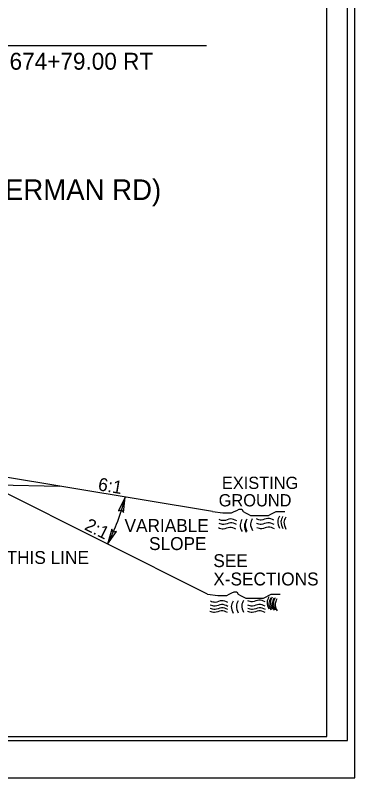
# Model space of a CAD drawing. Extents: x 2294370 to 2294957, y 719276 to 719941.
# Drawn here: x 2294750.8 to 2294792, y 719276.3 to 719368.6 of the extents above; entities that cross this region are included whole.
import ezdxf

# ---------------------------------------------------------------- set-up
doc = ezdxf.new("R2010")
doc.units = 0
for name, color, linetype in [('Old_Level_1', 7, 'Continuous'), ('Old_Level_11', 7, 'Continuous'), ('Old_Level_2', 7, 'Continuous'), ('Old_Level_3', 7, 'Continuous'), ('Sheet Cutting Line CELL', 7, 'Continuous'), ('Sheet Plot Border Inside CELL', 7, 'Continuous'), ('Sheet Plot Border Outside CELL', 7, 'Continuous'), ('Sheet Typical CELL', 7, 'Continuous'), ('Typical Hinge Slope Arterial CELL', 7, 'Continuous')]:
    doc.layers.add(name, color=color, linetype=linetype)

msp = doc.modelspace()

# ---------------------------------------------------------------- linework, layer by layer
at = {"layer": 'Old_Level_1'}
msp.add_line((2294740.816, 719311.96), (2294756.206, 719311.637), dxfattribs=at)
at = {"layer": 'Old_Level_11'}
msp.add_line((2294773.963, 719364.93), (2294713.602, 719364.929), dxfattribs=at)
for points in [[(2294763.92, 719308.46), (2294764.131, 719310.316), (2294763.299, 719308.63), (2294763.679, 719308.765)], [(2294762.493, 719306.42), (2294761.997, 719304.619), (2294763.081, 719306.155), (2294762.684, 719306.081)]]:
    msp.add_lwpolyline(points, close=True, dxfattribs=at)
at = {"layer": 'Old_Level_2'}
for points in [[(2294777.65, 719307.449), (2294776.896, 719307.664), (2294776.105, 719307.461), (2294775.53, 719307.588)], [(2294777.65, 719307.449), (2294776.896, 719307.664), (2294776.105, 719307.461), (2294775.53, 719307.588)], [(2294778.272, 719307.592), (2294778.06, 719306.97), (2294778.289, 719306.149)], [(2294778.788, 719307.506), (2294778.577, 719306.884), (2294778.805, 719306.062)], [(2294778.879, 719307.647), (2294778.667, 719307.025), (2294778.893, 719306.201)], [(2294778.879, 719307.647), (2294778.667, 719307.025), (2294778.893, 719306.201)], [(2294779.534, 719307.697), (2294779.325, 719307.077), (2294779.549, 719306.254)], [(2294779.534, 719307.697), (2294779.325, 719307.077), (2294779.549, 719306.254)], [(2294782.163, 719307.52), (2294781.414, 719307.736), (2294780.616, 719307.533), (2294780.046, 719307.662)], [(2294782.163, 719307.52), (2294781.414, 719307.736), (2294780.616, 719307.533), (2294780.046, 719307.662)], [(2294782.828, 719308.004), (2294782.615, 719307.382), (2294782.843, 719306.561)], [(2294782.828, 719308.004), (2294782.615, 719307.382), (2294782.843, 719306.561)], [(2294783.217, 719307.963), (2294783.008, 719307.341), (2294783.236, 719306.517)], [(2294783.217, 719307.963), (2294783.008, 719307.341), (2294783.236, 719306.517)], [(2294783.582, 719307.892), (2294783.37, 719307.272), (2294783.599, 719306.448)], [(2294783.582, 719307.892), (2294783.37, 719307.272), (2294783.599, 719306.448)], [(2294777.554, 719306.431), (2294776.802, 719306.646), (2294776.006, 719306.443), (2294775.434, 719306.572)], [(2294777.554, 719306.431), (2294776.802, 719306.646), (2294776.006, 719306.443), (2294775.434, 719306.572)], [(2294777.63, 719306.977), (2294776.877, 719307.194), (2294776.085, 719306.989), (2294775.511, 719307.118)], [(2294777.63, 719306.977), (2294776.877, 719307.194), (2294776.085, 719306.989), (2294775.511, 719307.118)], [(2294782.168, 719306.997), (2294781.414, 719307.21), (2294780.623, 719307.007), (2294780.05, 719307.136)], [(2294782.168, 719306.997), (2294781.414, 719307.21), (2294780.623, 719307.007), (2294780.05, 719307.136)], [(2294782.226, 719306.469), (2294781.474, 719306.681), (2294780.676, 719306.483), (2294780.104, 719306.609)], [(2294782.226, 719306.469), (2294781.474, 719306.681), (2294780.676, 719306.483), (2294780.104, 719306.609)], [(2294781.544, 719298.222), (2294781.331, 719297.6), (2294781.559, 719296.778)], [(2294781.933, 719298.181), (2294781.724, 719297.559), (2294781.952, 719296.735)], [(2294776.563, 719297.086), (2294775.809, 719297.303), (2294775.018, 719297.098), (2294774.443, 719297.227)], [(2294776.563, 719297.086), (2294775.809, 719297.303), (2294775.018, 719297.098), (2294774.443, 719297.227)], [(2294776.583, 719297.558), (2294775.829, 719297.773), (2294775.037, 719297.57), (2294774.463, 719297.697)], [(2294776.583, 719297.558), (2294775.829, 719297.773), (2294775.037, 719297.57), (2294774.463, 719297.697)], [(2294777.204, 719297.702), (2294776.993, 719297.079), (2294777.221, 719296.258)], [(2294777.204, 719297.702), (2294776.993, 719297.079), (2294777.221, 719296.258)], [(2294777.811, 719297.756), (2294777.6, 719297.134), (2294777.826, 719296.31)], [(2294777.811, 719297.756), (2294777.6, 719297.134), (2294777.826, 719296.31)], [(2294778.467, 719297.806), (2294778.258, 719297.186), (2294778.482, 719296.363)], [(2294778.467, 719297.806), (2294778.258, 719297.186), (2294778.482, 719296.363)], [(2294781.096, 719297.629), (2294780.346, 719297.845), (2294779.548, 719297.643), (2294778.978, 719297.772)], [(2294781.096, 719297.629), (2294780.346, 719297.845), (2294779.548, 719297.643), (2294778.978, 719297.772)], [(2294781.1, 719297.106), (2294780.347, 719297.319), (2294779.555, 719297.116), (2294778.983, 719297.245)], [(2294781.1, 719297.106), (2294780.347, 719297.319), (2294779.555, 719297.116), (2294778.983, 719297.245)], [(2294781.76, 719298.114), (2294781.547, 719297.491), (2294781.775, 719296.67)], [(2294782.149, 719298.073), (2294781.94, 719297.451), (2294782.168, 719296.626)], [(2294782.298, 719298.11), (2294782.086, 719297.49), (2294782.315, 719296.666)], [(2294782.514, 719298.001), (2294782.303, 719297.382), (2294782.531, 719296.558)], [(2294776.521, 719296.328), (2294775.769, 719296.541), (2294774.972, 719296.342), (2294774.399, 719296.469)], [(2294776.562, 719296.69), (2294775.81, 719296.905), (2294775.014, 719296.702), (2294774.442, 719296.831)], [(2294776.562, 719296.69), (2294775.81, 719296.905), (2294775.014, 719296.702), (2294774.442, 719296.831)], [(2294781.084, 719296.328), (2294780.332, 719296.541), (2294779.534, 719296.342), (2294778.962, 719296.469)], [(2294781.125, 719296.69), (2294780.373, 719296.905), (2294779.577, 719296.702), (2294779.005, 719296.831)], [(2294781.125, 719296.69), (2294780.373, 719296.905), (2294779.577, 719296.702), (2294779.005, 719296.831)]]:
    msp.add_spline(points, degree=3, dxfattribs=at)
at = {"layer": 'Sheet Cutting Line CELL'}
msp.add_line((2294455.16, 719276.338), (2294791.96, 719276.338), dxfattribs=at)
at = {"layer": 'Sheet Plot Border Inside CELL'}
msp.add_lwpolyline([(2294791.06, 719491.848), (2294457.76, 719491.848), (2294457.76, 719280.828), (2294791.06, 719280.828)], close=True, dxfattribs=at)
at = {"layer": 'Sheet Plot Border Outside CELL'}
for points in [[(2294455.16, 719276.338), (2294791.96, 719276.338), (2294791.96, 719496.338), (2294455.16, 719496.338)], [(2294791.96, 719496.338), (2294455.16, 719496.338), (2294455.16, 719276.338), (2294791.96, 719276.338)]]:
    msp.add_lwpolyline(points, close=True, dxfattribs=at)
at = {"layer": 'Sheet Typical CELL'}
msp.add_lwpolyline([(2294788.56, 719491.338), (2294488.56, 719491.338), (2294488.56, 719281.338), (2294788.56, 719281.338)], close=True, dxfattribs=at)
at = {"layer": 'Typical Hinge Slope Arterial CELL'}
for p in [(2294774.121, 719298.55), (2294774.715, 719308.552)]:
    msp.add_line(p, (2294743.816, 719313.702), dxfattribs=at)
for points in [[(2294774.715, 719308.552), (2294775.947, 719308.399), (2294776.255, 719308.399), (2294776.717, 719308.399), (2294777.025, 719308.399), (2294777.333, 719308.552), (2294777.641, 719308.706), (2294777.949, 719308.861), (2294778.257, 719308.861), (2294778.412, 719308.552), (2294778.72, 719308.399), (2294779.028, 719308.244), (2294779.336, 719308.091), (2294779.644, 719308.091), (2294779.951, 719308.091), (2294780.259, 719308.091), (2294780.567, 719308.091), (2294780.875, 719308.091), (2294781.183, 719308.091), (2294781.491, 719308.091), (2294781.799, 719308.244), (2294782.107, 719308.399), (2294782.415, 719308.552), (2294782.878, 719308.552), (2294783.186, 719308.552), (2294783.494, 719308.552)], [(2294774.121, 719298.55), (2294775.353, 719298.396), (2294775.66, 719298.396), (2294776.123, 719298.396), (2294776.431, 719298.396), (2294776.739, 719298.55), (2294777.047, 719298.704), (2294777.355, 719298.859), (2294777.663, 719298.859), (2294777.817, 719298.55), (2294778.125, 719298.396), (2294778.433, 719298.242), (2294778.741, 719298.088), (2294779.049, 719298.088), (2294779.357, 719298.088), (2294779.665, 719298.088), (2294779.973, 719298.088), (2294780.281, 719298.088), (2294780.589, 719298.088), (2294780.897, 719298.088), (2294781.205, 719298.242), (2294781.513, 719298.396), (2294781.821, 719298.55), (2294782.283, 719298.55), (2294782.591, 719298.55), (2294782.899, 719298.55)]]:
    msp.add_lwpolyline(points, dxfattribs=at)
msp.add_arc((2294736.108, 719317.563), 28.944, 333.43495, 345.5, dxfattribs=at)

# ---------------------------------------------------------------- texts
at = {"layer": 'Old_Level_1'}
for s, height, rotation, p in [('-L- Sta. 670+62.59 RT to Sta. 674+79.00 RT', 2.04545, 360, (2294713.539, 719362.051)), ('6:1', 1.5625, 350.53768, (2294760.76, 719311.148)), ('EXISTING', 1.4844, 0.00004, (2294775.849, 719311.294)), ('GROUND', 1.4844, 0.00004, (2294775.462, 719309.185)), ('2:1', 1.5625, 333.43495, (2294759.083, 719306.428)), ('SEE ', 1.5625, 359.99996, (2294774.805, 719301.837)), ('X-SECTIONS', 1.5625, 359.99996, (2294774.805, 719299.616))]:
    msp.add_text(s, height=height, rotation=rotation, dxfattribs=at).set_placement(p)
at = {"layer": 'Old_Level_11'}
msp.add_text('GRADE TO THIS LINE', height=1.5625, rotation=0.00004, dxfattribs=at).set_placement((2294738.251, 719302.221))
at = {"layer": 'Old_Level_3'}
msp.add_text('-Y- SR 1160 (MT HERMAN RD)', height=2.5, rotation=360, dxfattribs=at).set_placement((2294720.938, 719346.271))
at = {"layer": 'Typical Hinge Slope Arterial CELL'}
for s, p in [('VARIABLE ', (2294764.045, 719306.089)), ('SLOPE', (2294767.017, 719303.902))]:
    msp.add_text(s, height=1.5625, dxfattribs=at).set_placement(p)

doc.saveas('drawing.dxf')
